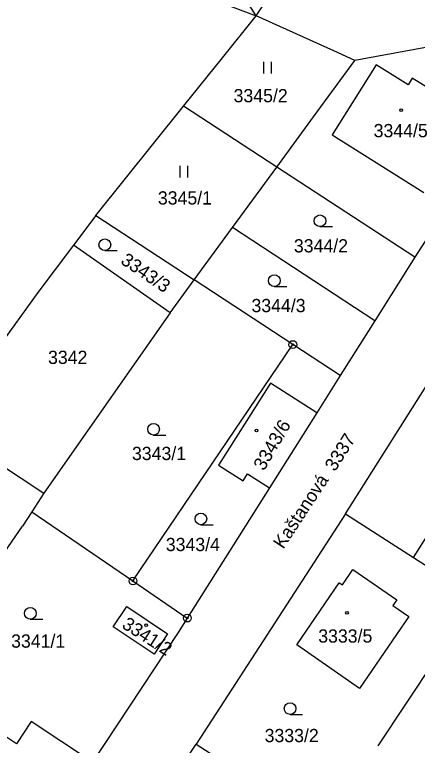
# Model space of a CAD drawing. Extents: x -755819 to -753140, y -1169796 to -1166000.
# Drawn here: x -754380.1 to -754328.4, y -1168813.6 to -1168719.7 of the extents above; entities that cross this region are included whole.
import ezdxf

# ---------------------------------------------------------------- set-up
doc = ezdxf.new("R2010")
doc.units = 0
for name, color, linetype in [('Vrstva 1', 7, 'Continuous'), ('Vrstva 15', 7, 'Continuous'), ('Vrstva 18', 7, 'Continuous'), ('Vrstva 19', 7, 'Continuous'), ('Vrstva 24', 7, 'Continuous'), ('Vrstva 25', 7, 'Continuous'), ('Vrstva 4', 7, 'Continuous'), ('Vrstva 6', 7, 'Continuous')]:
    doc.layers.add(name, color=color, linetype=linetype)

msp = doc.modelspace()

# ---------------------------------------------------------------- linework, layer by layer
at = {"layer": 'Vrstva 1'}
for p, q in [((-754349.08, -1168719.89), (-754341.3, -1168708.14)), ((-754376.74, -1168709.5), (-754349.08, -1168719.89)), ((-754353.41, -1168725.27), (-754349.08, -1168719.89)), ((-754339.12, -1168724.4), (-754349.08, -1168719.89)), ((-754309.63, -1168720.72), (-754336.39, -1168725.63)), ((-754336.39, -1168725.63), (-754339.12, -1168724.4)), ((-754358.42, -1168731.49), (-754353.41, -1168725.27)), ((-754341.71, -1168732.88), (-754336.39, -1168725.63)), ((-754333.67, -1168726.19), (-754339.33, -1168735.15)), ((-754329.55, -1168728.75), (-754333.67, -1168726.19)), ((-754329.03, -1168727.89), (-754329.55, -1168728.75)), ((-754321.32, -1168732.72), (-754329.03, -1168727.89)), ((-754369.71, -1168745.53), (-754358.42, -1168731.49)), ((-754346.43, -1168739.31), (-754358.42, -1168731.49)), ((-754346.43, -1168739.31), (-754341.71, -1168732.88)), ((-754339.33, -1168735.15), (-754327.53, -1168742.59)), ((-754352.13, -1168747.09), (-754346.43, -1168739.31)), ((-754328.68, -1168750.89), (-754346.43, -1168739.31)), ((-754324.41, -1168744.13), (-754328.68, -1168750.89)), ((-754369.71, -1168745.53), (-754372.58, -1168749.34)), ((-754369.71, -1168745.53), (-754357.05, -1168753.81)), ((-754357.05, -1168753.81), (-754352.13, -1168747.09)), ((-754333.83, -1168759.05), (-754352.13, -1168747.09)), ((-754372.58, -1168749.34), (-754377.16, -1168755.42)), ((-754360.14, -1168758.02), (-754372.58, -1168749.34)), ((-754328.68, -1168750.89), (-754333.83, -1168759.05)), ((-754360.14, -1168758.02), (-754357.05, -1168753.81)), ((-754344.38, -1168762.1), (-754357.05, -1168753.81)), ((-754377.16, -1168755.42), (-754389.49, -1168772.51)), ((-754360.14, -1168758.02), (-754364.55, -1168764.32)), ((-754333.83, -1168759.05), (-754338.3, -1168766.08)), ((-754364.93, -1168792.45), (-754344.38, -1168762.1)), ((-754338.3, -1168766.08), (-754344.38, -1168762.1)), ((-754337.63, -1168783.84), (-754323.59, -1168761.64)), ((-754364.55, -1168764.32), (-754376.38, -1168781.2)), ((-754338.3, -1168766.08), (-754341.31, -1168770.85)), ((-754347.27, -1168767.06), (-754353.94, -1168777.57)), ((-754341.31, -1168770.85), (-754347.27, -1168767.06)), ((-754341.31, -1168770.85), (-754347.38, -1168780.48)), ((-754389.49, -1168772.51), (-754376.38, -1168781.2)), ((-754353.94, -1168777.57), (-754350.78, -1168779.61)), ((-754350.78, -1168779.61), (-754350.19, -1168778.7)), ((-754350.19, -1168778.7), (-754347.38, -1168780.48)), ((-754347.38, -1168780.48), (-754357.94, -1168797.22)), ((-754376.38, -1168781.2), (-754377.93, -1168783.58)), ((-754377.93, -1168783.58), (-754379.13, -1168785.43)), ((-754377.93, -1168783.58), (-754364.93, -1168792.45)), ((-754337.63, -1168783.84), (-754356.8, -1168813.4)), ((-754337.63, -1168783.84), (-754328.89, -1168789.43)), ((-754392.76, -1168805.11), (-754379.13, -1168785.43)), ((-754328.89, -1168789.43), (-754326.63, -1168785.94)), ((-754328.89, -1168789.43), (-754321.87, -1168793.92)), ((-754338.01, -1168792.97), (-754336.65, -1168790.98)), ((-754336.65, -1168790.98), (-754331.02, -1168794.89)), ((-754364.93, -1168792.45), (-754357.94, -1168797.22)), ((-754343.86, -1168800.64), (-754338.41, -1168792.69)), ((-754338.41, -1168792.69), (-754338.01, -1168792.97)), ((-754331.02, -1168794.89), (-754331.54, -1168795.59)), ((-754367.47, -1168798.35), (-754365.73, -1168795.75)), ((-754365.73, -1168795.75), (-754360.48, -1168799.24)), ((-754331.54, -1168795.59), (-754329.45, -1168797.03)), ((-754329.45, -1168797.03), (-754335.79, -1168806.26)), ((-754357.94, -1168797.22), (-754359.12, -1168799.09)), ((-754362.21, -1168801.84), (-754367.47, -1168798.35)), ((-754359.12, -1168799.09), (-754370.14, -1168815.72)), ((-754360.48, -1168799.24), (-754362.21, -1168801.84)), ((-754335.79, -1168806.26), (-754343.86, -1168800.64)), ((-754333.42, -1168813.63), (-754325.72, -1168802.01)), ((-754367.49, -1168829.65), (-754356.8, -1168813.4)), ((-754356.8, -1168813.4), (-754340.43, -1168823.89))]:
    msp.add_line(p, q, dxfattribs=at)
at = {"layer": 'Vrstva 24'}
for centre, radius in [((-754344.38, -1168762.1), 0.5), ((-754344.38, -1168762.1), 0.1), ((-754364.93, -1168792.45), 0.5), ((-754364.93, -1168792.45), 0.1), ((-754357.94, -1168797.22), 0.5), ((-754357.94, -1168797.22), 0.1)]:
    msp.add_circle(centre, radius, dxfattribs=at)
at = {"layer": 'Vrstva 25'}
for p, q in [((-754348.1, -1168727.3), (-754348.1, -1168725.8)), ((-754347.1, -1168727.3), (-754347.1, -1168725.8)), ((-754358.87, -1168740.63), (-754358.87, -1168739.13)), ((-754357.87, -1168740.63), (-754357.87, -1168739.13)), ((-754340.89, -1168746.96), (-754339.29, -1168746.96)), ((-754368.54, -1168750.04), (-754366.94, -1168750.04)), ((-754346.76, -1168754.64), (-754345.16, -1168754.64)), ((-754362.28, -1168773.72), (-754360.68, -1168773.72)), ((-754356.2, -1168785.23), (-754354.6, -1168785.23)), ((-754378.12, -1168797.36), (-754376.52, -1168797.36)), ((-754344.73, -1168809.59), (-754343.13, -1168809.59))]:
    msp.add_line(p, q, dxfattribs=at)
for centre, radius in [((-754330.46, -1168731.99), 0.175), ((-754340.89, -1168746.21), 0.75), ((-754368.54, -1168749.29), 0.75), ((-754346.76, -1168753.89), 0.75), ((-754362.28, -1168772.97), 0.75), ((-754349.04, -1168773.12), 0.175), ((-754356.2, -1168784.48), 0.75), ((-754378.12, -1168796.61), 0.75), ((-754337.42, -1168796.55), 0.175), ((-754363.22, -1168798.13), 0.175), ((-754344.73, -1168808.84), 0.75)]:
    msp.add_circle(centre, radius, dxfattribs=at)
at = {"layer": 'Vrstva 4'}
for p, q in [((-754378.01, -1168810.48), (-754379.91, -1168813.36)), ((-754370.14, -1168815.72), (-754378.01, -1168810.48)), ((-754379.91, -1168813.36), (-754382.46, -1168811.69))]:
    msp.add_line(p, q, dxfattribs=at)
at = {"layer": 'Vrstva 6'}
msp.add_line((-754349.08, -1168719.89), (-754352, -1168715.3), dxfattribs=at)

# ---------------------------------------------------------------- texts
at = {"layer": 'Vrstva 15'}
msp.add_text('Kaštanová', height=1.7, rotation=56.72282, dxfattribs=at).set_placement((-754345.604, -1168788.452))
at = {"layer": 'Vrstva 18'}
for s, p in [('3345/2', (-754351.993, -1168730.99)), ('3345/1', (-754361.723, -1168744.12)), ('3344/2', (-754344.243, -1168750.27)), ('3344/3', (-754349.693, -1168757.94)), ('3342', (-754375.841, -1168764.59)), ('3343/1', (-754365.053, -1168776.93)), ('3343/4', (-754360.703, -1168788.62)), ('3341/1', (-754380.583, -1168801.02)), ('3333/2', (-754348.003, -1168813.15))]:
    msp.add_text(s, height=1.7, dxfattribs=at).set_placement(p)
for s, rotation, p in [('3343/3', 325.7838, (-754366.624, -1168751.613)), ('3337', 57.58226, (-754338.963, -1168778.49))]:
    msp.add_text(s, height=1.7, rotation=rotation, dxfattribs=at).set_placement(p)
at = {"layer": 'Vrstva 19'}
for s, p in [('3344/5', (-754333.992, -1168735.48)), ('3333/5', (-754341.113, -1168800.37))]:
    msp.add_text(s, height=1.7, dxfattribs=at).set_placement(p)
for s, rotation, p in [('3343/6', 59.64491, (-754348.085, -1168778.398)), ('3341/2', 327.38808, (-754366.466, -1168798.396))]:
    msp.add_text(s, height=1.7, rotation=rotation, dxfattribs=at).set_placement(p)

doc.saveas('drawing.dxf')
